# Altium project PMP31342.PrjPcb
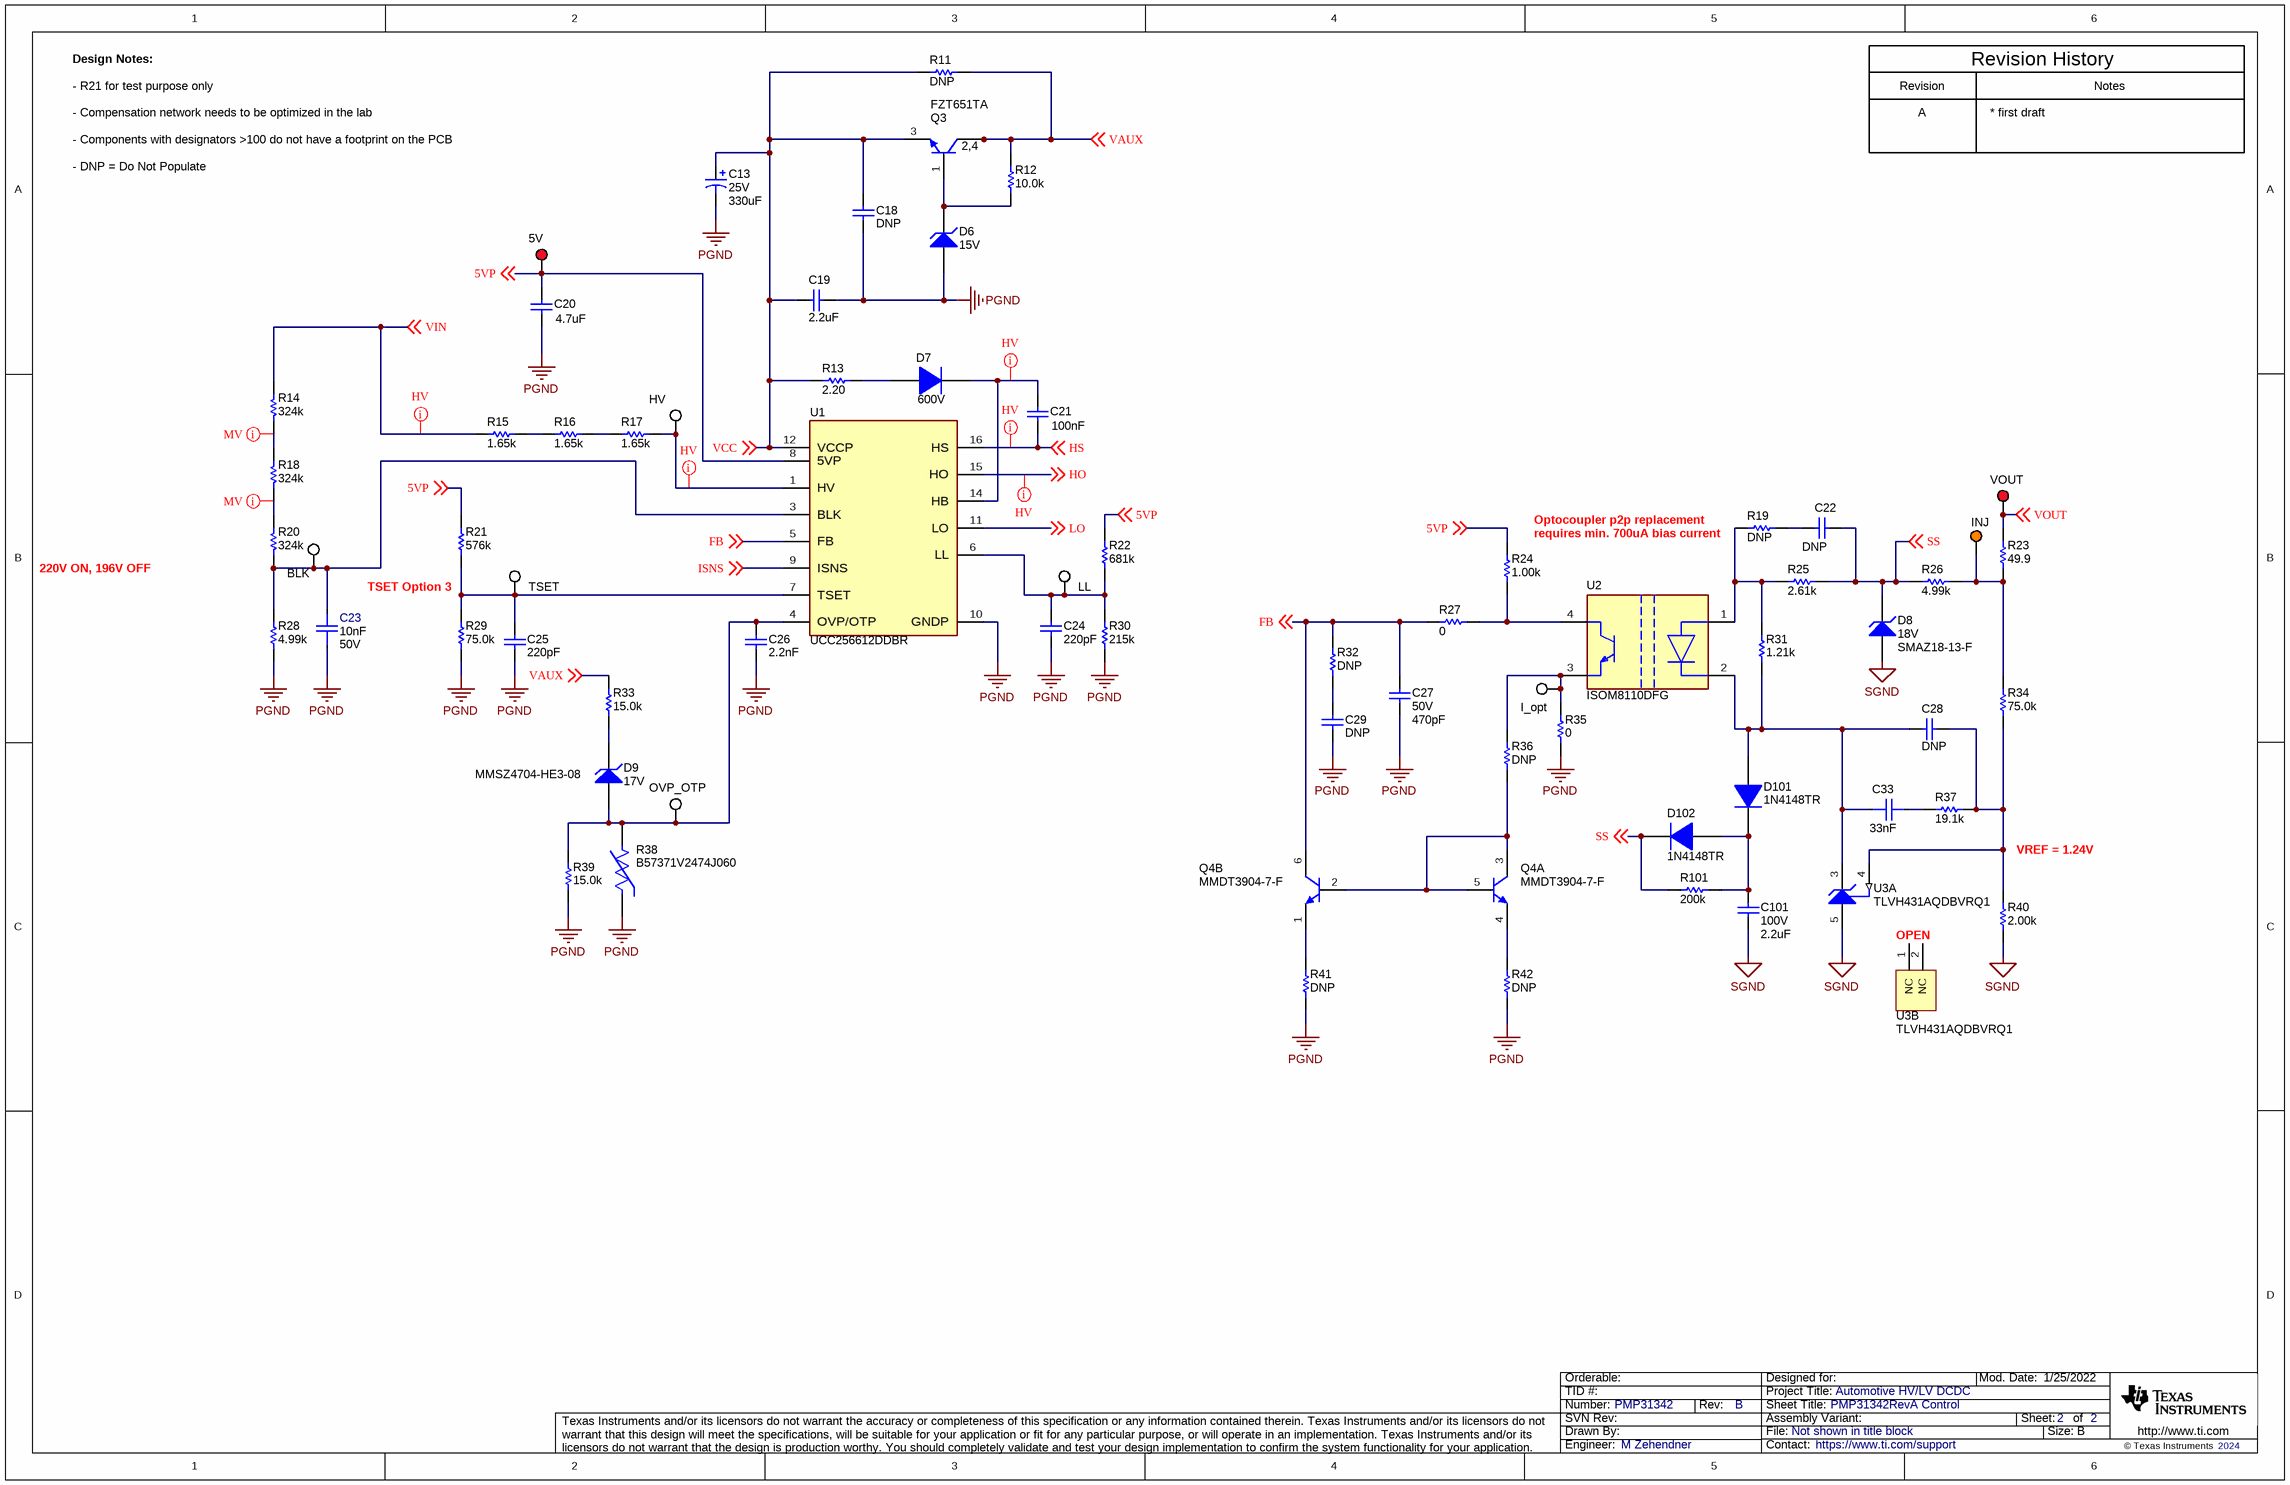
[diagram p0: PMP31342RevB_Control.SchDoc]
CopyrightYear: 2024; PRJ_Engineer: M Zehendner; PRJ_Number: PMP31342; PRJ_Title: Automotive HV/LV DCDC; SCH_Rev: B; TechSupport: https://www.ti.com/support
2 sheets, 137 parts. Net scope: global (net labels, ports and power ports of the same name join across sheets).
Board file: PMP31342RevA_PCB.PcbDoc
Sheets:
  PMP31342RevB_Control.SchDoc
  PMP31342RevB_PowerStage.SchDoc

## Sheet PMP31342RevB_Control.SchDoc: PMP31342RevA Control
size 431 x 279 mm; Date: Not shown in title block; ApprovedBy: Not shown in title block; CheckedBy: Not shown in title block; Author: Not shown in title block; CompanyName: Not shown in title block; Engineer: Not shown in title block; Organization: Not shown in title block; Address1: Not shown in title block; Address2: Not shown in title block; Address3: Not shown in title block; Address4: Not shown in title block; DocumentNumber: 2; Revision: Use project parameter SCH_Rev; SheetNumber: 2; SheetTotal: 2; PageSetup: Record=PageOptions¦CenterHorizontal=True¦CenterVertical=True¦PrintScale=1.00¦XCorrection=1.00¦YCorrection=1.00¦PrintKind=0¦BorderSize=5000000¦LeftOffset=0¦BottomOffset=0¦Orientation=2¦PaperLength=1000¦PaperWidth=1000¦Scale=100¦PaperSource=15¦PrintQuality=600¦MediaType=1¦DitherType=10¦PaperKind=Letter¦PrintScaleMode=1

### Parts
5V  5010  [Keystone5010]  (value not drawn)
BLK  5012  [Keystone5012]  (value not drawn)
C13  VDC_V: 25V  ValueDisplayed: 330uF  [SM_RADIAL_F]  (hidden comment: EEE-FK1E331P)
C18  ValueDisplayed: DNP  [0805L]  (hidden comment: C2012X7R1V225K085AC)
C19  ValueDisplayed: 2.2uF  [0805L]  (hidden comment: C2012X7R1V225K085AC)
C20  ValueDisplayed: 4.7uF  [1206L]  (hidden comment: C3216X7R1E475K085AB)
C21  Cap_F: 100nF  [1206_180L]  (hidden comment: GRM31C5C1E104JA01L)
C22  ValueDisplayed: DNP  [0603L]  (hidden comment: C0603C472J1GAC7867)
C23  Cap_F: 10nF  VDC_V: 50V  [FP-CGA3E2X7R1H103K080AA_0603-MFG]  (hidden comment: CGA3E2X7R1H103K080AA)
C24  Cap_F: 220pF  [0603]  (hidden comment: GRM188R72E221KW07D)
C25  Cap_F: 220pF  [0603]  (hidden comment: C0603X221K5RACTU)
C26  Cap_F: 2.2nF  [0603]  (hidden comment: C0603X222K5RACTU)
C27  VDC_V: 50V  ValueDisplayed: 470pF  [1206]  (hidden comment: CC1206KRX7R9BB471)
C28  Cap_F: DNP  [0603]  (hidden comment: GRM188R72A681KA01D)
C29  Cap_F: DNP  [0603]  (hidden comment: C0603X102K5RACTU)
C33  Cap_F: 33nF  [FP-CGA3E2X7R1H333K080AA_0603-MFG]  (hidden comment: CGA3E2X7R1H333K080AA)
C101  VDC_V: 100V  ValueDisplayed: 2.2uF  [1210_250]  (hidden comment: CGA6N3X7R2A225K230AB)
D6  value 15V  [SOD-123]  (hidden comment: MMSZ4702-HE3-08)
D7  Vr_V: 600V  [SMAF]  (hidden comment: ES1JAF)
D8  SMAZ18-13-F  value 18V  [SMA]
D9  MMSZ4704-HE3-08  value 17V  [SOD-123]
D101  1N4148TR  [DO-35]
D102  1N4148TR  [DO-35]
HV  5012  [Keystone5012]  (value not drawn)
I_opt  5012  [Keystone5012]  (value not drawn)
INJ  5013  [Keystone5013]  (value not drawn)
LL  5012  [Keystone5012]  (value not drawn)
OVP_OTP  5012  [Keystone5012]  (value not drawn)
Q3  FZT651TA  [SOT-223]
Q4  MMDT3904-7-F  [SOT-363]  (parts A,B of 2)
R11  ValueDisplayed: DNP  [0805_HV]  (hidden comment: CRCW08050000Z0EAHP)
R12  ValueDisplayed: 10.0k  [0603]  (hidden comment: CRCW060310K0FKEA)
R13  ValueDisplayed: 2.20  [0603L]  (hidden comment: ERJ-3RQF2R2V)
R14  ValueDisplayed: 324k  [1206]  (hidden comment: CRCW1206324KFKEA)
R15  ValueDisplayed: 1.65k  [1206L]  (hidden comment: CRCW12061K65FKEA)
R16  ValueDisplayed: 1.65k  [1206L]  (hidden comment: CRCW12061K65FKEA)
R17  ValueDisplayed: 1.65k  [1206L]  (hidden comment: CRCW12061K65FKEA)
R18  ValueDisplayed: 324k  [1206]  (hidden comment: CRCW1206324KFKEA)
R19  ValueDisplayed: DNP  [0603L]  (hidden comment: RC0603FR-071K21L)
R20  ValueDisplayed: 324k  [1206]  (hidden comment: CRCW1206324KFKEA)
R21  ValueDisplayed: 576k  [0603]  (hidden comment: CRCW0603576KFKEA)
R22  ValueDisplayed: 681k  [0603]  (hidden comment: CRCW0603681KFKEA)
R23  ValueDisplayed: 49.9  [0603]  (hidden comment: CRCW060349R9FKEA)
R24  ValueDisplayed: 1.00k  [0603]  (hidden comment: CRCW06031K00FKEA)
R25  ValueDisplayed: 2.61k  [0603]  (hidden comment: CRCW06032K61FKEA)
R26  ValueDisplayed: 4.99k  [0603]  (hidden comment: CRCW06034K99FKEA)
R27  ValueDisplayed: 0  [0402]  (hidden comment: CRCW04020000Z0ED)
R28  ValueDisplayed: 4.99k  [0603]  (hidden comment: CRCW06034K99FKEA)
R29  ValueDisplayed: 75.0k  [0603]  (hidden comment: CRCW060375K0FKEA)
R30  ValueDisplayed: 215k  [0603]  (hidden comment: CRCW0603215KFKEA)
R31  ValueDisplayed: 1.21k  [0603]  (hidden comment: CRCW06031K21FKEA)
R32  ValueDisplayed: DNP  [0603]  (hidden comment: CRCW06034K99FKEA)
R33  ValueDisplayed: 15.0k  [0603]  (hidden comment: RG1608P-153-B-T5)
R34  ValueDisplayed: 75.0k  [0603]  (hidden comment: CRCW060375K0FKEA)
R35  ValueDisplayed: 0  [0603]  (hidden comment: CRCW06030000Z0EA)
R36  ValueDisplayed: DNP  [0603]  (hidden comment: CRCW06030000Z0EA)
R37  ValueDisplayed: 19.1k  [0603]  (hidden comment: CRCW060319K1FKEA)
R38  B57371V2474J060  [FP-B57371V2474J060_0603-MFG]
R39  ValueDisplayed: 15.0k  [0603]  (hidden comment: RG1608P-153-B-T5)
R40  ValueDisplayed: 2.00k  [0603]  (hidden comment: CRCW06032K00FKEA)
R41  ValueDisplayed: DNP  [0603]  (hidden comment: CRCW06030000Z0EA)
R42  ValueDisplayed: DNP  [0603]  (hidden comment: CRCW06030000Z0EA)
R101  ValueDisplayed: 200k  [0402]  (hidden comment: CRCW0402200KJNED)
TSET  5012  [Keystone5012]  (value not drawn)
U1  PartNumber: UCC256612DDBR  [DDB0014A-MFG]  (hidden comment: UCC256602DDBR)
U2  ISOM8110DFG  [DFG0004A-MFG]
U3  TLVH431AQDBVRQ1  [DBV0005A_N]  (parts A,B of 2)
VOUT  5010  [Keystone5010]  (value not drawn)

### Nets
PGND: C13.2(-) C18.1 C19.2 C20.2 C23.1 C24.2 C25.2 C26.2 C27.2 C29.2 D6.2(A) R28.1 R29.1 R30.1 R35.1 R38.1 R39.1 R41.1 R42.1 U1.10(GNDP)
SGND: C101.2 D8.2(A) R40.1 U3.5(ANODE)
5VP: 5V.1 C20.1 R21.2 R22.2 R24.2 U1.8(5VP) ; off-sheet 5VP
FB: C27.1 Q4.6(C) R27.1 R32.2 U1.5(FB) ; off-sheet FB
HO: U1.15(HO) ; off-sheet HO
HS: C21.2 U1.16(HS) ; off-sheet HS
ISNS: U1.9(ISNS) ; off-sheet ISNS
LO: U1.11(LO) ; off-sheet LO
SS: C22.1 D8.1(K) D102.1(K) R25.2 R26.1 R101.1 ; off-sheet SS
VAUX: Q3.2(C) Q3.4(C) R11.2 R12.2 R33.2 ; off-sheet VAUX
VCC: C13.1(+) C18.2 C19.1 Q3.3(E) R11.1 R13.1 U1.12(VCCP) ; off-sheet VCC
VIN: R14.2 R15.1 ; off-sheet VIN
VOUT: R23.2 VOUT.1 ; off-sheet VOUT
NetBLK_1: BLK.1 C23.2 R20.1 R28.2 U1.3(BLK)
NetC21_1: C21.1 D7.1(K) U1.14(HB)
NetC22_2: C22.2 R19.2
NetC24_1: C24.1 LL.1 R22.1 R30.2 U1.6(LL)
NetC25_1: C25.1 R21.1 R29.2 TSET.1 U1.7(TSET)
NetC26_1: C26.1 D9.2(A) OVP_OTP.1 R38.2 R39.2 U1.4(OVP/OTP)
NetC28_1: C28.1 R34.1 R37.2 R40.2 U3.4(REF)
NetC28_2: C28.2 C33.1 D101.2(A) R31.1 U2.2(CAT) U3.3(CATHODE)
NetC29_1: C29.1 R32.1
NetC33_2: C33.2 R37.1
NetC101_1: C101.1 D101.1(K) D102.2(A) R101.2
NetD6_1: D6.1(K) Q3.1(B) R12.1
NetD7_2: D7.2(A) R13.2
NetD9_1: D9.1(K) R33.1
NetHV_1: HV.1 R17.2 U1.1(HV)
NetI_opt_1: I_opt.1 R35.2 R36.2 U2.3(Emitter)
NetINJ_1: INJ.1 R23.1 R26.2 R34.2
NetQ4_1: Q4.1(E) R41.2
NetQ4_2: Q4.2(B) Q4.3(C) Q4.5(B) R36.1
NetQ4_4: Q4.4(E) R42.2
NetR14_1: R14.1 R18.2
NetR15_2: R15.2 R16.1
NetR16_2: R16.2 R17.1
NetR18_1: R18.1 R20.2
NetR19_1: R19.1 R25.1 R31.2 U2.1(AN)
NetR24_1: R24.1 R27.2 U2.4(Collector)

Not connected (* = marked no-connect by the designer): U3 1(NC) 2(NC)

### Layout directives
net class HV: HO, HS, NetC21_1, NetHV_1, VIN
net class MV: NetR14_1, NetR18_1

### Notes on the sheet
- Design Notes:
- - R21 for test purpose only
- Revision
- Revision History
- Notes
- - DNP = Do Not Populate
- - Compensation network needs to be optimized in the lab
- - Components with designators >100 do not have a footprint on the PCB
- A
- * first draft
- (near R20) 220V ON, 196V OFF
- Optocoupler p2p replacement
- requires min. 700uA bias current
- TSET Option 3
- VREF = 1.24V
- (near U3) OPEN

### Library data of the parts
5V VOUT = CMP-0055147-2: Test Point, Multipurpose, Red, TH; Manufacturer: Keystone Electronics; CNHeader: FALSE; Green_Lifecycle: Active; Green_REACh: Passed; ContactFinish: Silver; CT: TRUE
BLK HV I_opt LL OVP_OTP TSET = CMP-0055149-2: Test Point, Multipurpose, White, TH; Manufacturer: Keystone Electronics; CNHeader: FALSE; Green_Lifecycle: Active; Green_REACh: Passed; ContactFinish: Silver; CT: TRUE
C13 = CMP-0010717-1: CAP, AL, 330 uF, 25 V, +/- 20%, 0.16 ohm, AEC-Q200 Grade 2, SMD; Manufacturer: Panasonic; TaMin_C: -55°C; ESR_ohm: 0.16; Polarized: Y; SizeAreaWB_mm2: 123.6; U/M: EA; Value: 330uF; TaMax_C: 105°C; SizeZ_mm: 10.2; SizeX_mm: 10; SizeY_mm: 8.3; Cap_Case: F; SizeArea_mm2: 83; CompType: Capacitor; Cap_F: 330µF; IRMS_A: 600mA; AEC Grade: 2; AEC Category: Q200
C18 C19 = CMP-0007883-2: CAP, CERM, 2.2 uF, 35 V, +/- 10%, X7R, 0805; Manufacturer: TDK; TaMin_C: -55°C; Polarized: N; SizeAreaWB_mm2: 6.75; Value1: Unknown; U/M: EA; Value: 2.2uF; TaMax_C: 125°C; SizeZ_mm: 1.45; SizeX_mm: 2; SizeY_mm: 1.25; Cap_Case: 0805; Value2: 35V; SizeArea_mm2: 2.5; CompType: Capacitor; Cap_F: 2.2µF; AEC Category: Q200
C20 = CMP-0008693-2: CAP, CERM, 4.7 uF, 25 V, +/- 10%, X7R, 1206; Manufacturer: TDK; TaMin_C: -55°C; Polarized: N; SizeAreaWB_mm2: 10.92; Value1: Unknown; U/M: EA; Value: 4.7uF; TaMax_C: 125°C; SizeZ_mm: 1.35; SizeX_mm: 3.2; SizeY_mm: 1.6; Cap_Case: 1206; Value2: 25V; SizeArea_mm2: 5.12; CompType: Capacitor; Cap_F: 4.7µF; AEC Category: Q200
C21 = CMP-0064950-2: CAP, CERM, 0.1 uF, 25 V,+/- 5%, C0G/NP0, 1206; Manufacturer: MuRata; TaMin_C: -55°C; Polarized: N; SizeAreaWB_mm2: 10.92; Value1: Unknown; U/M: EA; Value: 0.1uF; TaMax_C: 125°C; SizeZ_mm: 1.8; SizeX_mm: 3.2; SizeY_mm: 1.6; Cap_Case: 1206; Value2: 25V; SizeArea_mm2: 5.12; AEC Category: Q200
C22 = CMP-0006941-4: CAP, CERM, 4700 pF, 100 V, +/- 5%, C0G/NP0, 0603; Manufacturer: Kemet; TaMin_C: -55°C; Polarized: N; SizeAreaWB_mm2: 4.68; Value1: Unknown; U/M: EA; Value: 4700pF; TaMax_C: 125°C; SizeZ_mm: 1; SizeX_mm: 1.6; SizeY_mm: 0.8; Cap_Case: 0603; Value2: 100V; SizeArea_mm2: 1.28; Cap_F: 4.7nF; AEC Category: Q200
C23 = CMP-0097473-1: Cap Ceramic 10nF 50V X7R 10% Pad SMD 0603 +125°C Automotive T/R; Manufacturer: TDK; TempCo: 0.15; AEC Grade: Grade 1; Tolerance_%: 0.1%; AEC Qualified: Yes; SizeZ_mm: 1.1mm
C24 = CMP-0007492-4: CAP, CERM, 220 pF, 250 V, +/- 10%, X7R, 0603; Manufacturer: MuRata; TaMin_C: -55°C; Polarized: N; SizeAreaWB_mm2: 4.68; Value1: Unknown; U/M: EA; Value: 220pF; TaMax_C: 125°C; SizeZ_mm: 1; SizeX_mm: 1.6; SizeY_mm: 0.8; Value2: 250V; SizeArea_mm2: 1.28; AEC Category: Q200
C25 = CMP-0006982-4: CAP, CERM, 220 pF, 50 V, +/- 10%, X7R, 0603; Manufacturer: Kemet; TaMin_C: -55°C; Polarized: N; SizeAreaWB_mm2: 4.68; Value1: Unknown; U/M: EA; Value: 220pF; TaMax_C: 125°C; SizeZ_mm: 1; SizeX_mm: 1.6; SizeY_mm: 0.8; Value2: 50V; SizeArea_mm2: 1.28; AEC Category: Q200
C26 = CMP-0006983-4: CAP, CERM, 2200 pF, 50 V, +/- 10%, X7R, 0603; Manufacturer: Kemet; TaMin_C: -55°C; Polarized: N; SizeAreaWB_mm2: 4.68; Value1: Unknown; U/M: EA; Value: 2200pF; TaMax_C: 125°C; SizeZ_mm: 1; SizeX_mm: 1.6; SizeY_mm: 0.8; Value2: 50V; SizeArea_mm2: 1.28; AEC Category: Q200
C27 = CMP-0008758-2: CAP, CERM, 470 pF, 50 V, +/- 10%, X7R, 1206; Manufacturer: Yageo America; TaMin_C: -55°C; Polarized: N; SizeAreaWB_mm2: 10.92; Value1: Unknown; U/M: EA; Value: 470pF; TaMax_C: 125°C; SizeZ_mm: 1.35; SizeX_mm: 3.2; SizeY_mm: 1.6; SizeArea_mm2: 5.12; AEC Category: Q200
C28 = CMP-0007486-5: CAP, CERM, 680 pF, 100 V, +/- 10%, X7R, 0603; Manufacturer: MuRata; TaMin_C: -55°C; Polarized: N; SizeAreaWB_mm2: 4.68; Value1: Unknown; U/M: EA; Value: 680pF; TaMax_C: 125°C; SizeZ_mm: 1; SizeX_mm: 1.6; SizeY_mm: 0.8; Value2: 100V; SizeArea_mm2: 1.28; AEC Category: Q200
C29 = CMP-0006976-5: CAP, CERM, 1000 pF, 50 V, +/- 10%, X7R, 0603; Manufacturer: Kemet; TaMin_C: -55°C; Polarized: N; SizeAreaWB_mm2: 4.68; Value1: Unknown; U/M: EA; Value: 1000pF; TaMax_C: 125°C; SizeZ_mm: 1; SizeX_mm: 1.6; SizeY_mm: 0.8; Value2: 50V; SizeArea_mm2: 1.28; AEC Category: Q200
C33 = CMP-0090210-1: Cap Ceramic 33nF 50V X7R 10% Pad SMD 0603 +125°C Automotive T/R; Manufacturer: TDK; AEC Qualified: Yes; AEC Grade: Grade 1; Tolerance_%: 0.1%; TempCo: 0.15; SizeZ_mm: 1.1mm
C101 = CMP-0009152-2: CAP, CERM, 2.2 uF, 100 V, +/- 10%, X7R, AEC-Q200 Grade 1,; Manufacturer: TDK; TaMin_C: -55°C; ESR_ohm: 1.73m; Polarized: N; SizeAreaWB_mm2: 14.7; Value1: 0.00173 ohm; U/M: EA; Value: 2.2uF; TaMax_C: 125°C; SizeZ_mm: 2.5; SizeX_mm: 3.2; SizeArea_mm2: 8; AEC Qualified: Y; Cap_F: 2.2µF; IRMS_A: 5.5932A; AEC Grade: 1; AEC Category: Q200
D6 = CMP-0077575-3: Diode, Zener, 15 V, 500 mW, AEC-Q101, SOD-123; Manufacturer: Vishay-Semiconductor; SizeAreaWB_mm2: 13.095; Power_W: 500mW; AEC Category: Q101; SizeX_mm: 3.85; Value1: 0.5W; SizeZ_mm: 1.35; AEC Qualified: Y; SizeY_mm: 1.7; SizeArea_mm2: 6.545; RJA_CperW: 340
D7 = CMP-0029162-2: Diode, Ultrafast, 600 V, 1 A, AEC-Q101, SMAF; Manufacturer: Fairchild Semiconductor; Io_A: 1A; Green_Lifecycle: Not Set; SizeAreaWB_mm2: 19.95; Green_REACh: Incomplete; TJmax_C: 150°C; Value: 600V; SizeZ_mm: 1; SizeX_mm: 4.7; SizeY_mm: 2.5; Vf_V: 1.7V; SizeArea_mm2: 11.75; AEC Qualified: Y; AEC Category: Q101
D8 = CMP-0005526-4: Diode, Zener, 18 V, 1 W, AEC-Q101, SMA; Manufacturer: Diodes Inc.; SizeAreaWB_mm2: 37.3428; AEC Category: Q101; Power_W: 1W; SizeY_mm: 2.92; SizeZ_mm: 2.87; SizeX_mm: 5.59; SizeArea_mm2: 16.3228; AEC Qualified: Y; RJA_CperW: 125
D9 = CMP-0077577-3: Diode, Zener, 17 V, 500 mW, AEC-Q101, SOD-123; Manufacturer: Vishay-Semiconductor; SizeX_mm: 3.85; Power_W: 500mW; SizeY_mm: 1.7; AEC Category: Q101; SizeAreaWB_mm2: 13.095; Value1: 0.5W; SizeArea_mm2: 6.545; AEC Qualified: Y; SizeZ_mm: 1.35; RJA_CperW: 340
D101 D102 = CMP-0029198-2: Diode, P-N, 100 V, 0.2 A, TH; Manufacturer: Fairchild Semiconductor; SizeArea_mm2: 13.95; Vr_V: 100V; SizeX_mm: 9.3; Value: 100V; SizeY_mm: 1.5; Io_A: 200mA; TJmax_C: 175°C; AEC Qualified: N; AEC Category: Q101; Value1: 0.2A; SizeZ_mm: 1.7; SizeAreaWB_mm2: 39.55
INJ = CMP-0055150-2: Test Point, Multipurpose, Orange, TH; Manufacturer: Keystone Electronics; CNHeader: FALSE; Green_Lifecycle: Active; Green_REACh: Passed; ContactFinish: Silver; CT: TRUE
Q3 = CMP-0000393-2: Transistor, NPN, 60 V, 3 A, SOT-223; Manufacturer: Zetex; TaMax_C: 150°C; Value2: 300; Value1: 3 A; Vcesat1_V: 430mV; SizeX_mm: 6.5; SizeY_mm: 7; TaMin_C: -55°C; IcRated_A: 3A; CompType: BJT; SizeZ_mm: 1.6; Value: 60 V; SizeArea_mm2: 45.5; NPN: 1; Vceo_V: 60V; PNP: 0; AEC Category: Q101; SizeAreaWB_mm2: 76.5; U/M: EA
Q4 = CMP-0000396-2: Transistor, Dual NPN, 40 V, 0.2 A, SOT-363; Manufacturer: Diodes Inc.; TaMax_C: 150°C; Value2: 300; Value1: 0.2 A; Vcesat1_V: 300mV; SizeX_mm: 2.2; TaMin_C: -55°C; IcRated_A: 200mA; CompType: BJT; SizeZ_mm: 1.1; Value: 40 V; SizeArea_mm2: 4.84; NPN: 2; Vceo_V: 40V; PNP: 0; AEC Category: Q101; SizeAreaWB_mm2: 10.24; U/M: EA
R11 = CMP-0020443-3: RES, 0, 5%, 0.333 W, AEC-Q200 Grade 0, 0805; Manufacturer: Vishay-Dale; Power_W: 333mW; TempCo: 200 ppm/C; Value_Code: 0000; Value: 0; EIA_Code: E24; SizeX_mm: 2; SizeY_mm: 1.25; SizeZ_mm: 1.45; Value2: 0.333W; SizeArea_mm2: 2.5; AEC Qualified: Y; AEC Category: Q200; VDC_V: 150V
R12 = CMP-0021998-4: RES, 10.0 k, 1%, 0.1 W, AEC-Q200 Grade 0, 0603; Manufacturer: Vishay-Dale; Power_W: 100mW; TempCo: 100 ppm/C; Value_Code: 10k0; Value: 10.0k; EIA_Code: E96; Res_ohm: 10k; SizeX_mm: 1.6; SizeY_mm: 0.8; SizeZ_mm: 1; Value2: 0.1W; SizeArea_mm2: 1.28; AEC Qualified: Y; VDC_V: 75V; AEC Category: Q200; AEC Grade: 0
R13 = CMP-0022711-2: RES, 2.20, 1%, 0.1 W, 0603; Manufacturer: Panasonic; Power_W: 100mW; TempCo: 200 ppm/C; Value_Code: 2R20; U/M: EA; Value: 2.20; Res_ohm: 2.2; SizeX_mm: 1.6; SizeY_mm: 0.8; SizeZ_mm: 1; Value2: 0.1W; SizeArea_mm2: 1.28; CompType: Resistor; AEC Category: Q200
R14 R18 R20 = CMP-0016907-3: RES, 324 k, 1%, 0.25 W, AEC-Q200 Grade 0, 1206; Manufacturer: Vishay-Dale; Power_W: 250mW; TempCo: 100 ppm/C; Value: 324k; EIA_Code: E96; SizeX_mm: 3.2; SizeY_mm: 1.6; SizeZ_mm: 1.35; Value2: 0.25W; SizeArea_mm2: 5.12; AEC Qualified: Y; VDC_V: 200V; AEC Category: Q200; AEC Grade: 0
R15-R17 = CMP-0016708-3: RES, 1.65 k, 1%, 0.25 W, AEC-Q200 Grade 0, 1206; Manufacturer: Vishay-Dale; Power_W: 250mW; TempCo: 100 ppm/C; Value_Code: 1k65; Value: 1.65k; EIA_Code: E96; SizeX_mm: 3.2; SizeY_mm: 1.6; SizeZ_mm: 1.35; Value2: 0.25W; SizeArea_mm2: 5.12; CompType: Resistor; AEC Qualified: Y; VDC_V: 200V; AEC Category: Q200; AEC Grade: 0
R19 = CMP-0022871-5: RES, 1.21 k, 1%, 0.1 W, 0603; Manufacturer: Yageo; Power_W: 100mW; TempCo: 100 ppm/C; Value_Code: 1k21; Value: 1.21k; EIA_Code: E96; SizeX_mm: 1.6; SizeY_mm: 0.8; SizeZ_mm: 1; Value2: 0.1W; SizeArea_mm2: 1.28; AEC Qualified: N; VDC_V: 75V; AEC Category: Q200; SizeAreaWB_mm2: 4.68
R21 = CMP-0022501-4: RES, 576 k, 1%, 0.1 W, AEC-Q200 Grade 0, 0603; Manufacturer: Vishay-Dale; Power_W: 100mW; TempCo: 100 ppm/C; Value: 576k; EIA_Code: E96; SizeX_mm: 1.6; SizeY_mm: 0.8; SizeZ_mm: 1; Value2: 0.1W; SizeArea_mm2: 1.28; AEC Qualified: Y; VDC_V: 75V; AEC Category: Q200; AEC Grade: 0
R22 = CMP-0022550-4: RES, 681 k, 1%, 0.1 W, AEC-Q200 Grade 0, 0603; Manufacturer: Vishay-Dale; Power_W: 100mW; TempCo: 100 ppm/C; Value: 681k; EIA_Code: E96; SizeX_mm: 1.6; SizeY_mm: 0.8; SizeZ_mm: 1; Value2: 0.1W; SizeArea_mm2: 1.28; AEC Qualified: Y; VDC_V: 75V; AEC Category: Q200; AEC Grade: 0
R23 = CMP-0022448-4: RES, 49.9, 1%, 0.1 W, AEC-Q200 Grade 0, 0603; Manufacturer: Vishay-Dale; Power_W: 100mW; TempCo: 100 ppm/C; Value_Code: 49R9; Value: 49.9; EIA_Code: E96; SizeX_mm: 1.6; SizeY_mm: 0.8; SizeZ_mm: 1; Value2: 0.1W; SizeArea_mm2: 1.28; AEC Qualified: Y; VDC_V: 75V; AEC Category: Q200; AEC Grade: 0
R24 = CMP-0022109-5: RES, 1.00 k, 1%, 0.1 W, AEC-Q200 Grade 0, 0603; Manufacturer: Vishay-Dale; Power_W: 100mW; TempCo: 100 ppm/C; Value_Code: 1k00; Value: 1.00k; EIA_Code: E96; Res_ohm: 1k; SizeX_mm: 1.6; SizeY_mm: 0.8; SizeZ_mm: 1; Value2: 0.1W; SizeArea_mm2: 1.28; AEC Qualified: Y; VDC_V: 75V; AEC Category: Q200; AEC Grade: 0
R25 = CMP-0022279-4: RES, 2.61 k, 1%, 0.1 W, AEC-Q200 Grade 0, 0603; Manufacturer: Vishay-Dale; Power_W: 100mW; TempCo: 100 ppm/C; Value_Code: 2k61; Value: 2.61k; EIA_Code: E96; SizeX_mm: 1.6; SizeY_mm: 0.8; SizeZ_mm: 1; Value2: 0.1W; SizeArea_mm2: 1.28; AEC Qualified: Y; VDC_V: 75V; AEC Category: Q200; AEC Grade: 0
R26 R28 R32 = CMP-0022458-4: RES, 4.99 k, 1%, 0.1 W, AEC-Q200 Grade 0, 0603; Manufacturer: Vishay-Dale; Power_W: 100mW; TempCo: 100 ppm/C; Value_Code: 4k99; Value: 4.99k; EIA_Code: E96; SizeX_mm: 1.6; SizeY_mm: 0.8; SizeZ_mm: 1; Value2: 0.1W; SizeArea_mm2: 1.28; AEC Qualified: Y; VDC_V: 75V; AEC Category: Q200; AEC Grade: 0
R27 = CMP-0026822-3: RES, 0, 5%, 0.063 W, AEC-Q200 Grade 0, 0402; Manufacturer: Vishay-Dale; Power_W: 63mW; TempCo: 200 ppm/C; Value_Code: 0000; Value: 0; EIA_Code: E24; SizeX_mm: 1; SizeY_mm: 0.5; SizeZ_mm: 0.6; Value2: 0.063W; AEC Qualified: Y; VDC_V: 50V; AEC Category: Q200
R29 R34 = CMP-0022589-4: RES, 75.0 k, 1%, 0.1 W, AEC-Q200 Grade 0, 0603; Manufacturer: Vishay-Dale; Power_W: 100mW; TempCo: 100 ppm/C; Value_Code: 75k0; Value: 75.0k; EIA_Code: E96; Res_ohm: 75k; SizeX_mm: 1.6; SizeY_mm: 0.8; SizeZ_mm: 1; Value2: 0.1W; SizeArea_mm2: 1.28; AEC Qualified: Y; VDC_V: 75V; AEC Category: Q200; AEC Grade: 0
R30 = CMP-0022210-4: RES, 215 k, 1%, 0.1 W, AEC-Q200 Grade 0, 0603; Manufacturer: Vishay-Dale; Power_W: 100mW; TempCo: 100 ppm/C; Value: 215k; EIA_Code: E96; SizeX_mm: 1.6; SizeY_mm: 0.8; SizeZ_mm: 1; Value2: 0.1W; SizeArea_mm2: 1.28; AEC Qualified: Y; VDC_V: 75V; AEC Category: Q200; AEC Grade: 0
R31 = CMP-0022117-4: RES, 1.21 k, 1%, 0.1 W, AEC-Q200 Grade 0, 0603; Manufacturer: Vishay-Dale; Power_W: 100mW; TempCo: 100 ppm/C; Value_Code: 1k21; Value: 1.21k; EIA_Code: E96; SizeX_mm: 1.6; SizeY_mm: 0.8; SizeZ_mm: 1; Value2: 0.1W; SizeArea_mm2: 1.28; AEC Qualified: Y; VDC_V: 75V; AEC Category: Q200; AEC Grade: 0
R33 R39 = CMP-0023441-3: RES, 15.0 k, 0.1%, 0.1 W, 0603; Manufacturer: Susumu Co Ltd; Power_W: 100mW; TempCo: 25 ppm/C; Value_Code: 15k0; U/M: EA; Value: 15.0k; EIA_Code: E192; Res_ohm: 15k; SizeX_mm: 1.6; SizeY_mm: 0.8; SizeZ_mm: 1; Value2: 0.1W; SizeArea_mm2: 1.28; VDC_V: 75V; AEC Category: Q200
R35 R36 R41 R42 = CMP-0025697-4: RES, 0, 5%, 0.1 W, AEC-Q200 Grade 0, 0603; Manufacturer: Vishay-Dale; Power_W: 100mW; TempCo: 200 ppm/C; Value_Code: 0000; Value: 0; EIA_Code: E24; SizeX_mm: 1.6; SizeY_mm: 0.8; SizeZ_mm: 1; Value2: 0.1W; SizeArea_mm2: 1.28; AEC Qualified: Y; VDC_V: 75V; AEC Category: Q200
R37 = CMP-0022105-4: RES, 19.1 k, 1%, 0.1 W, AEC-Q200 Grade 0, 0603; Manufacturer: Vishay-Dale; Power_W: 100mW; TempCo: 100 ppm/C; Value_Code: 19k1; Value: 19.1k; EIA_Code: E96; SizeX_mm: 1.6; SizeY_mm: 0.8; SizeZ_mm: 1; Value2: 0.1W; SizeArea_mm2: 1.28; AEC Qualified: Y; VDC_V: 75V; AEC Category: Q200; AEC Grade: 0
R38 = CMP-0096703-1: NTC Thermistor 470k 0603 (1608 Metric); Manufacturer: TDK; AEC Qualified: No; Res_ohm: 470kΩ; Power_W: 180mW; B 25 50: 4386K; B 25 100: 4480K; SizeZ_mm: 0.9mm; B 25 85: 4455K; B Tolerance: 3%; Tolerance_%: 5%
R40 = CMP-0022268-4: RES, 2.00 k, 1%, 0.1 W, AEC-Q200 Grade 0, 0603; Manufacturer: Vishay-Dale; Power_W: 100mW; TempCo: 100 ppm/C; Value_Code: 2k00; Value: 2.00k; EIA_Code: E96; Res_ohm: 2k; SizeX_mm: 1.6; SizeY_mm: 0.8; SizeZ_mm: 1; Value2: 0.1W; SizeArea_mm2: 1.28; AEC Qualified: Y; VDC_V: 75V; AEC Category: Q200; AEC Grade: 0
R101 = CMP-0026873-2: RES, 200 k, 5%, 0.063 W, AEC-Q200 Grade 0, 0402; Manufacturer: Vishay-Dale; Power_W: 63mW; TempCo: 200 ppm/C; Value: 200k; EIA_Code: E24; SizeX_mm: 1; SizeY_mm: 0.5; SizeZ_mm: 0.6; Value2: 0.063W; AEC Qualified: Y; VDC_V: 50V; AEC Category: Q200; AEC Grade: 0
U1 = CMP-0095298-2: 750kHz Wide VIN/VOUT Range LLC Controller Optimized for Light Load Efficiency; Manufacturer: Texas Instruments; Output Type: Other; Switching Frequency: 30-750kHz; TJmax_C: +150°C; SizeZ_mm: 1.75mm; AEC Qualified: No; Standoff Height: 0.1mm; Number Of Outputs: 2; TaMax_C: +125°C; TaMin_C: -40°C; Max Supply Voltage: 18.5V; AEC Category: Q200; CompType: IC
U2 = CMP-0098363-1: 3.75-kVRMS, Single-Channel Opto-Emulator with Transistor Output; Manufacturer: Texas Instruments; SizeZ_mm: 2.65mm; AEC Qualified: No; CTR (Max): 160%; CTR (Min): 80%; Emiiter Collector Voltage: 7V; Forward Current: 10mA; Power_TotalModule: 200mW; Standoff Height: 0.05mm; TaMax_C: +125°C; TaMin_C: -55°C; TJmax_C: +150°C; Turn Off Delay Time: 5us; Turn On Delay Time: 1.7us; Value: 80V; Vf_V: 1.1V; Voltage_Isolation_Vrms: 3750Vrms
U3 = CMP-0032955-1: Automotive Catalog Low-Voltage Adjustable Precision Shunt Regulator, 80 mA, -40 to 125 degC, 5-pin SOT-23 (DBV), Green (RoHS & no Sb/Br); Manufacturer: Texas Instruments; Iout/Iz(Max)(mA): 80; VO Adj(Max)(V): 18; SubFamily: Shunt Voltage Reference; Temp Coeff(Max)(ppm/ degree C): 129; VO Adj(Min)(V): 1.24; Initial Accuracy @ 25/deg C(%): 1

## Sheet PMP31342RevB_PowerStage.SchDoc: PMP31342RevA Power Stage
size 431 x 279 mm; Date: Not shown in title block; ApprovedBy: Not shown in title block; CheckedBy: Not shown in title block; Author: Not shown in title block; CompanyName: Not shown in title block; Engineer: Not shown in title block; Organization: Not shown in title block; Address1: Not shown in title block; Address2: Not shown in title block; Address3: Not shown in title block; Address4: Not shown in title block; DocumentNumber: 1; Revision: Use project parameter SCH_Rev; SheetNumber: 1; SheetTotal: 2; PageSetup: Record=PageOptions¦CenterHorizontal=True¦CenterVertical=True¦PrintScale=1.00¦XCorrection=1.00¦YCorrection=1.00¦PrintKind=0¦BorderSize=5000000¦LeftOffset=0¦BottomOffset=0¦Orientation=2¦PaperLength=1000¦PaperWidth=1000¦Scale=100¦PaperSource=15¦PrintQuality=600¦MediaType=1¦DitherType=10¦PaperKind=Letter¦PrintScaleMode=1
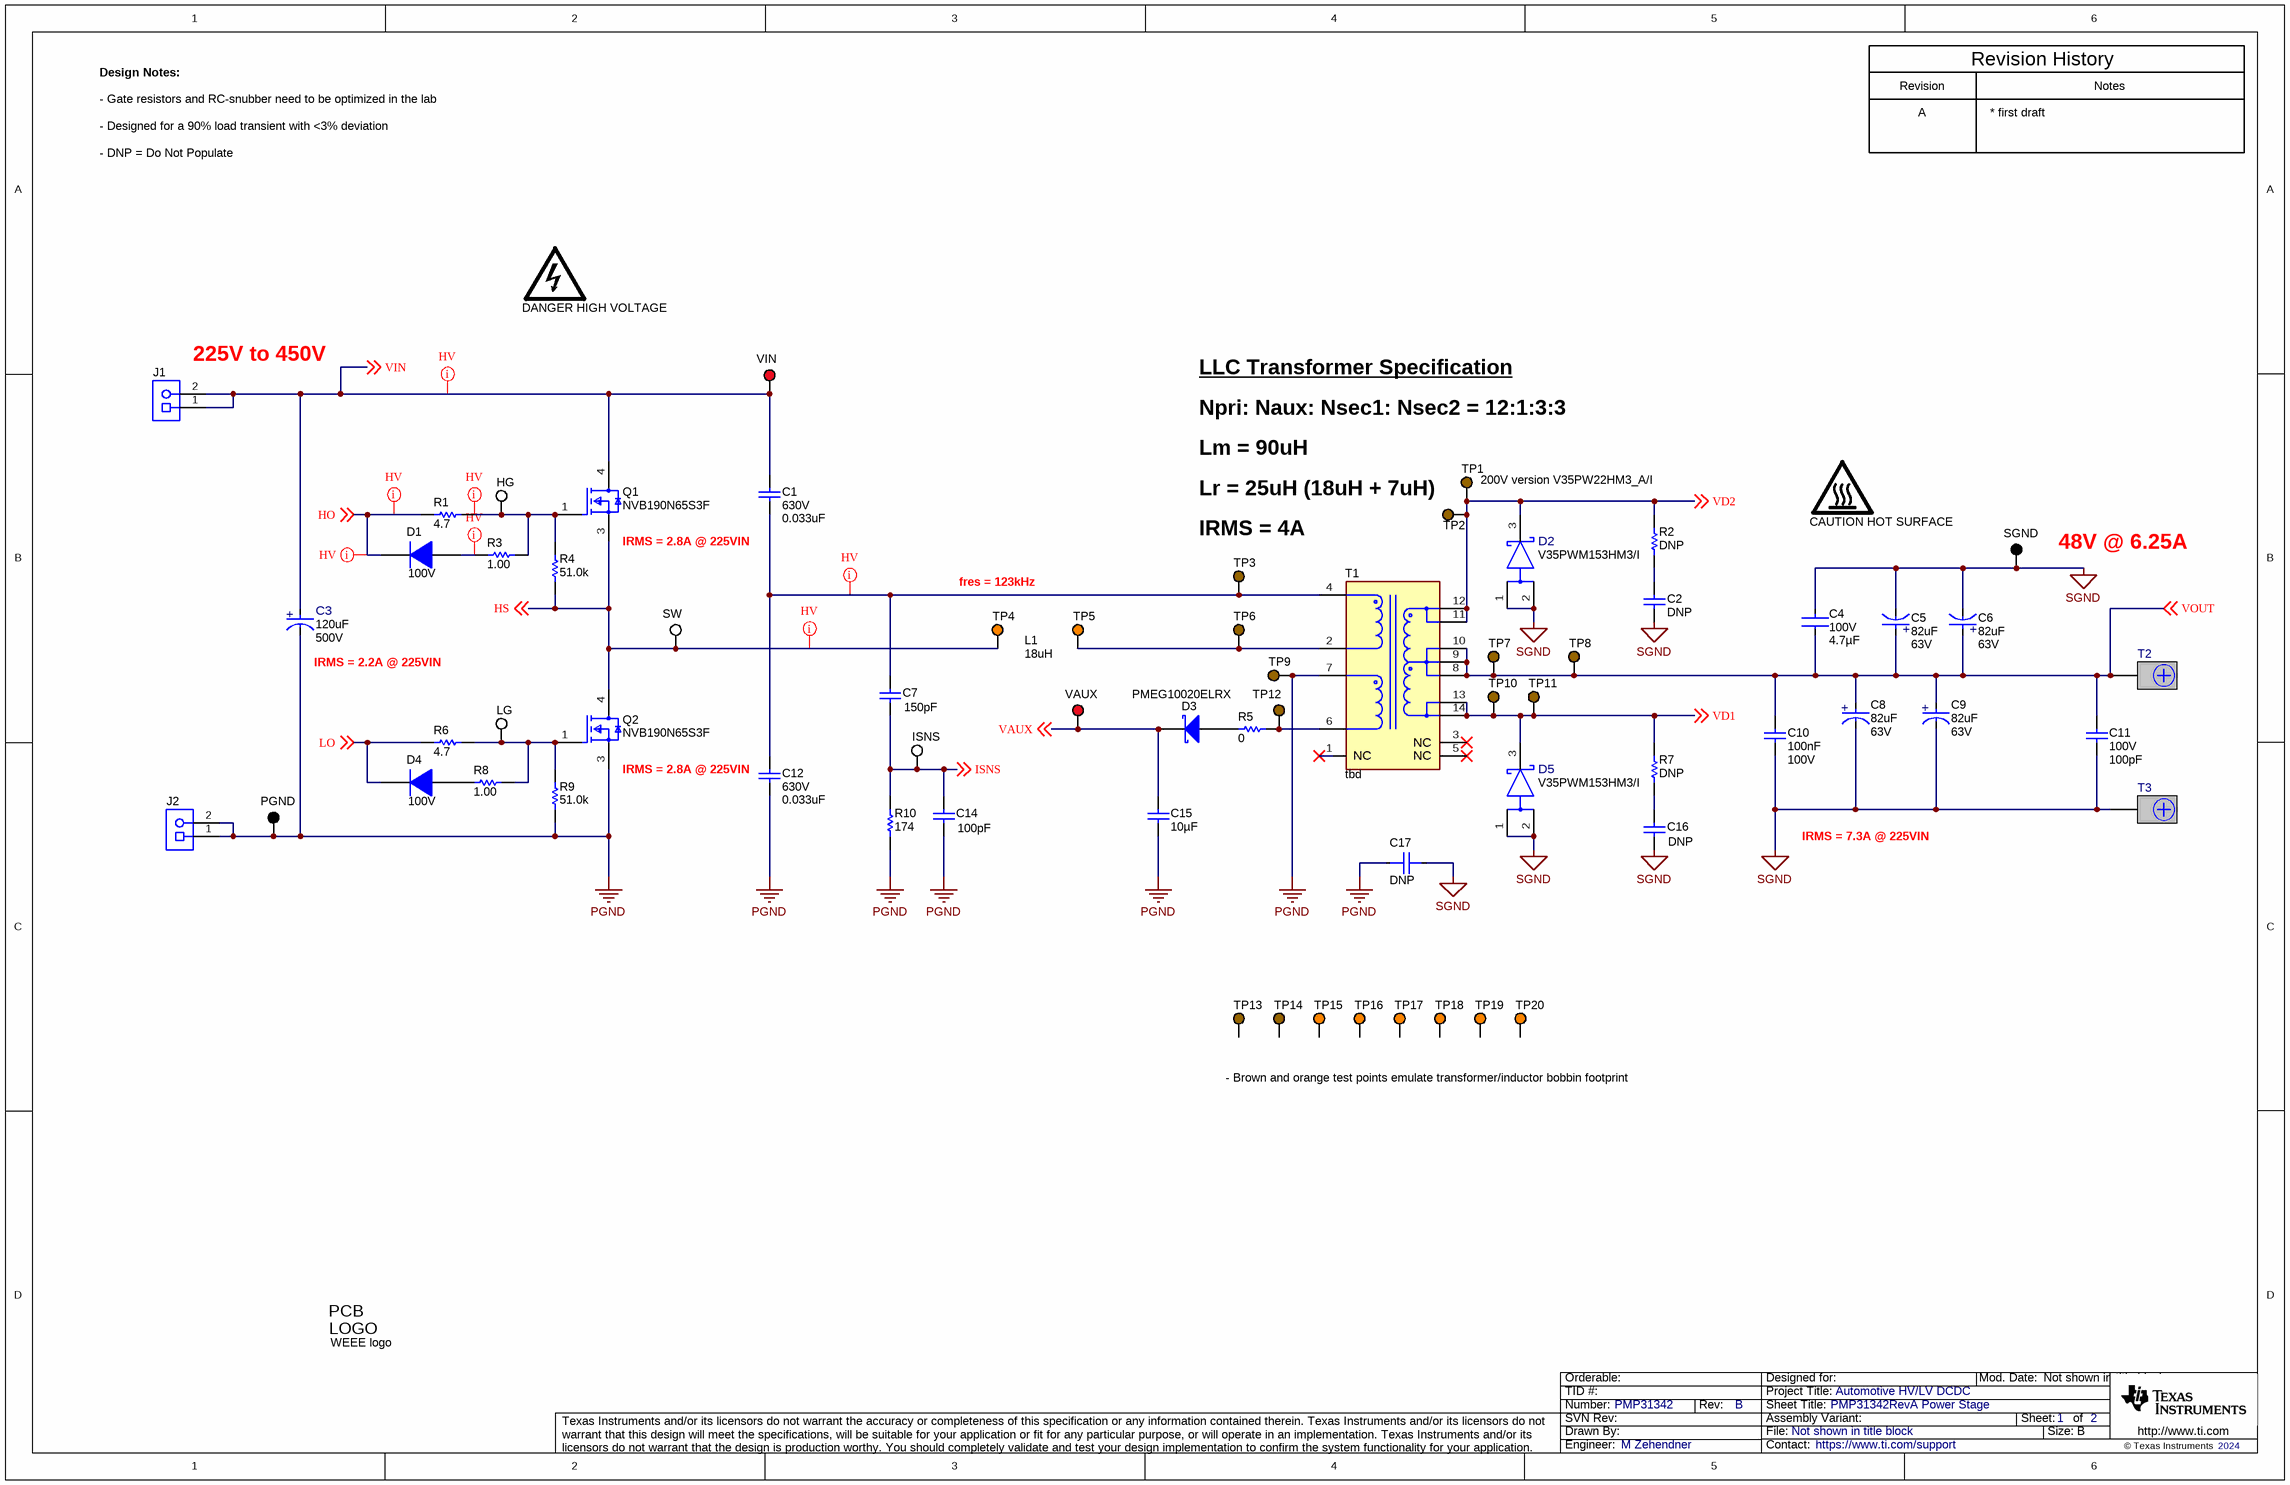
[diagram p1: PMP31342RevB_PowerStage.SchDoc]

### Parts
C1  VDC_V: 630V  ValueDisplayed: 0.033uF  [CAPRR1500W80L1800T500H1050]  (hidden comment: B32641B6333)
C2  ValueDisplayed: DNP  [0805L]  (hidden comment: GRM2165C2A122JA01D)
C3  ValueDisplayed: 120uF  VDC_V: 500V  [FP-ALA8AD121BC500_RADIAL-MFG]  (hidden comment: ALA8AD121BC500)
C4  Cap_F: 4.7µF  VDC_V: 100V  [FP-CNA6P1X7R2A475K250AE_1210-MFG]  (hidden comment: CNA6P1X7R2A475K250AE)
C5  ValueDisplayed: 82uF  VDC_V: 63V  [FP-HHXF630ARA820MJA0G_RADIAL-MFG]  (hidden comment: HHXF630ARA820MJA0G)
C6  ValueDisplayed: 82uF  VDC_V: 63V  [FP-HHXF630ARA820MJA0G_RADIAL-MFG]  (hidden comment: HHXF630ARA820MJA0G)
C7  ValueDisplayed: 150pF  [1206L]  (hidden comment: GRM31A5C2J151JW01D)
C8  ValueDisplayed: 82uF  VDC_V: 63V  [FP-HHXF630ARA820MJA0G_RADIAL-MFG]  (hidden comment: HHXF630ARA820MJA0G)
C9  ValueDisplayed: 82uF  VDC_V: 63V  [FP-HHXF630ARA820MJA0G_RADIAL-MFG]  (hidden comment: HHXF630ARA820MJA0G)
C10  Cap_F: 100nF  VDC_V: 100V  [0805_HV]  (hidden comment: GCM21BR72A104KA37L)
C11  VDC_V: 100V  ValueDisplayed: 100pF  [0805_HV]  (hidden comment: GCM2165C2A101JA16D)
C12  VDC_V: 630V  ValueDisplayed: 0.033uF  [CAPRR1500W80L1800T500H1050]  (hidden comment: B32641B6333)
C14  ValueDisplayed: 100pF  [1206L]  (hidden comment: 12061A101JAT2A)
C15  ValueDisplayed: 10µF  [1206_180]  (hidden comment: C1206C106J3RACAUTO)
C16  ValueDisplayed: DNP  [0805L]  (hidden comment: GRM2165C2A122JA01D)
C17  ValueDisplayed: DNP  [FP-CS95ZU2GA332MANKA_RADIAL-MFG]  (hidden comment: CS95ZU2GA332MANKA)
D1  Vr_V: 100V  [SOD-123]  (hidden comment: 1N4148W-7-F)
D2  V35PWM153HM3/I  [FP-V35PWM153-M3_I_TO-252AE-MFG]
D3  PMEG10020ELRX  [SOD-123W]
D4  Vr_V: 100V  [SOD-123]  (hidden comment: 1N4148W-7-F)
D5  V35PWM153HM3/I  [FP-V35PWM153-M3_I_TO-252AE-MFG]
HG  5012  [Keystone5012]  (value not drawn)
ISNS  5012  [Keystone5012]  (value not drawn)
J1  ED120/2DS  [On-Shore_ED120_2DS]  (value not drawn)
J2  ED120/2DS  [On-Shore_ED120_2DS]  (value not drawn)
LG  5012  [Keystone5012]  (value not drawn)
LOGO1  DANGER HIGH VOLTAGE  [IEC_HighVoltage_Small]  (no BOM)
Logo2  CAUTION HOT SURFACE  [IEC_HotSurface_Small]  (no BOM)
Logo3  WEEE logo  [WEEE_Minimum]  (no BOM)
PGND  5011  [Keystone5011]  (value not drawn)
Q1  NVB190N65S3F  [FP-FDD86252_D2PAK-MFG]
Q2  NVB190N65S3F  [FP-FDD86252_D2PAK-MFG]
R1  ValueDisplayed: 4.7  [0603]  (hidden comment: CRCW06034R70JNEA)
R2  ValueDisplayed: DNP  [1206L]  (hidden comment: RC1206FR-0710RL)
R3  ValueDisplayed: 1.00  [0603L]  (hidden comment: RC0603FR-071RL)
R4  ValueDisplayed: 51.0k  [0603L]  (hidden comment: RC0603FR-0751KL)
R5  ValueDisplayed: 0  [1206L]  (hidden comment: ERJ-8GEY0R00V)
R6  ValueDisplayed: 4.7  [0603]  (hidden comment: CRCW06034R70JNEA)
R7  ValueDisplayed: DNP  [1206L]  (hidden comment: RC1206FR-0710RL)
R8  ValueDisplayed: 1.00  [0603L]  (hidden comment: RC0603FR-071RL)
R9  ValueDisplayed: 51.0k  [0603L]  (hidden comment: RC0603FR-0751KL)
R10  ValueDisplayed: 174  [1206]  (hidden comment: CRCW1206174RFKEA)
SGND  5011  [Keystone5011]  (value not drawn)
SW  5012  [Keystone5012]  (value not drawn)
T1  tbd  [FP-750320617_PTH_XFRMR_36MM5_43MM0-MFG]
T2  CXS70-14-C  [Panduit_CXS70-14-C]  (value not drawn)
T3  CXS70-14-C  [Panduit_CXS70-14-C]  (value not drawn)
TP1  5125  [Keystone5125]  (value not drawn)
TP2  5125  [Keystone5125]  (value not drawn)
TP3  5125  [Keystone5125]  (value not drawn)
TP4  5003  [Keystone5003]  (value not drawn)
TP5  5003  [Keystone5003]  (value not drawn)
TP6  5125  [Keystone5125]  (value not drawn)
TP7  5125  [Keystone5125]  (value not drawn)
TP8  5125  [Keystone5125]  (value not drawn)
TP9  5125  [Keystone5125]  (value not drawn)
TP10  5125  [Keystone5125]  (value not drawn)
TP11  5125  [Keystone5125]  (value not drawn)
TP12  5125  [Keystone5125]  (value not drawn)
TP13  5125  [Keystone5125]  (value not drawn)
TP14  5125  [Keystone5125]  (value not drawn)
TP15  5003  [Keystone5003]  (value not drawn)
TP16  5003  [Keystone5003]  (value not drawn)
TP17  5003  [Keystone5003]  (value not drawn)
TP18  5003  [Keystone5003]  (value not drawn)
TP19  5003  [Keystone5003]  (value not drawn)
TP20  5003  [Keystone5003]  (value not drawn)
VAUX  5010  [Keystone5010]  (value not drawn)
VIN  5010  [Keystone5010]  (value not drawn)

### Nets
PGND: C3.1(CATHODE) C12.2 C14.2 C15.2 C17.1 J2.1 J2.2 PGND.1 Q2.3(S) R9.1 R10.1 T1.7 TP9.1
SGND: C2.2 C4.1 C5.1(CATHODE) C6.1(CATHODE) C8.1(CATHODE) C9.1(CATHODE) C10.2 C11.2 C16.2 C17.2 D2.1(ANODE) D2.2(ANODE) D5.1(ANODE) D5.2(ANODE) SGND.1 T3.1
HO: D1.1(K) R1.1 ; off-sheet HO
HS: Q1.3(S) Q2.4(D) R4.1 SW.1 TP4.1 ; off-sheet HS
ISNS: C7.2 C14.1 ISNS.1 R10.2 ; off-sheet ISNS
LO: D4.1(K) R6.1 ; off-sheet LO
VAUX: C15.1 D3.1(K) VAUX.1 ; off-sheet VAUX
VD1: D5.3(CATHODE) R7.2 T1.13 T1.14 TP10.1 TP11.1 ; off-sheet VD1
VD2: D2.3(CATHODE) R2.2 T1.11 T1.12 TP1.1 TP2.1 ; off-sheet VD2
VIN: C1.1 C3.2(ANODE) J1.1 J1.2 Q1.4(D) VIN.1 ; off-sheet VIN
VOUT: C4.2 C5.2(ANODE) C6.2(ANODE) C8.2(ANODE) C9.2(ANODE) C10.1 C11.1 T1.8 T1.9 T1.10 T2.1 TP7.1 TP8.1 ; off-sheet VOUT
NetC1_2: C1.2 C7.1 C12.1 T1.4 TP3.1
NetC2_1: C2.1 R2.1
NetC16_1: C16.1 R7.1
NetD1_2: D1.2(A) R3.1
NetD3_2: D3.2(A) R5.1
NetD4_2: D4.2(A) R8.1
NetHG_1: HG.1 Q1.1(G) R1.2 R3.2 R4.2
NetLG_1: LG.1 Q2.1(G) R6.2 R8.2 R9.2
NetR5_2: R5.2 T1.6 TP12.1
NetT1_2: T1.2 TP5.1 TP6.1

Not connected (* = marked no-connect by the designer): T1 1(NC)* 3(NC)* 5(NC)*; TP13 1; TP14 1; TP15 1; TP16 1; TP17 1; TP18 1; TP19 1; TP20 1

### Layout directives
net class HV: HO, HS, NetC1_2, NetD1_2, NetHG_1, VIN

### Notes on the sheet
- Design Notes:
- - Gate resistors and RC-snubber need to be optimized in the lab
- Revision
- Revision History
- Notes
- - DNP = Do Not Populate
- - Designed for a 90% load transient with <3% deviation
- A
- * first draft
- (near J1) 225V to 450V
- LLC Transformer Specification
- Npri: Naux: Nsec1: Nsec2 = 12:1:3:3
- Lm = 90uH
- Lr = 25uH (18uH + 7uH)
- (near TP1) 200V version V35PW22HM3_A/I
- (near Q1) IRMS = 2.8A @ 225VIN
- (near TP3) IRMS = 4A
- (near SGND) 48V @ 6.25A
- fres = 123kHz
- (near C3) IRMS = 2.2A @ 225VIN
- 18uH
- L1
- IRMS = 2.8A @ 225VIN
- IRMS = 7.3A @ 225VIN
- - Brown and orange test points emulate transformer/inductor bobbin footprint

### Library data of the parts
C1 C12 = CMP-0012454-3: CAP, Film, 0.033 uF, 630 V, +/- 10%, TH; Manufacturer: TDK; TaMin_C: -40°C; Polarized: N; SizeAreaWB_mm2: 140; Value1: Unknown; TaMax_C: 105°C; SizeZ_mm: 13.0; SizeX_mm: 14; SizeY_mm: 6; Cap_Case: CAP_14x13.0x6mm; AEC Qualified: Y; Cap_F: 33nF; AEC Category: Q200
C2 C16 = CMP-0008098-2: CAP, CERM, 1200 pF, 100 V, +/- 5%, C0G/NP0, 0805; Manufacturer: MuRata; TaMin_C: -55°C; Polarized: N; SizeAreaWB_mm2: 6.75; Value1: Unknown; U/M: EA; Value: 1200pF; TaMax_C: 125°C; SizeZ_mm: 1.45; SizeX_mm: 2; SizeY_mm: 1.25; Cap_Case: 0805; Value2: 100V; SizeArea_mm2: 2.5; Cap_F: 1.2nF; AEC Category: Q200
C3 = CMP-0122768-1: 120 µF 500 V Aluminum Electrolytic Capacitors Radial, Can - Snap-In 1.73Ohm @ 100Hz 5000 Hrs @ 105°C; Manufacturer: KEMET; AEC Grade: Grade 2; AEC Qualified: Yes; Cap_F: 120µF; IRMS_A: 1.1A; SizeZ_mm: 37mm; Tolerance_%: 20%; Esr: 1.73; Leakage Current: 180uA; Life: 5000Hours; Value: 120µF
C4 = CMP-0087262-1: CAP CER 4.7UF 100V X7R 1210; Manufacturer: TDK; Tolerance_%: 10%; TempCo: 15%; Symbol Name: SYM-CNA6P1X7R2A475K250AE; AEC Qualified: Yes; AEC Grade: Grade 1; SizeZ_mm: 2.8mm
C5 C6 C8 C9 = CMP-0122751-1: 82 µF 63 V Aluminum - Polymer Capacitors Radial, Can - SMD 22mOhm 3000 Hrs @ 135°C; Manufacturer: United Chemi-Con; AEC Grade: Grade 1; AEC Qualified: Yes; Cap_F: 82µF; IRMS_A: 4A; SizeZ_mm: 10.5mm; Tolerance_%: 20%; Dissipation Factor: 8%; Esr: 22m; Leakage Current: 51.6uA; Life: 4000Hours; Value: 82µF
C7 = CMP-0008885-2: CAP, CERM, 150 pF, 630 V, +/- 5%, C0G/NP0, 1206; Manufacturer: MuRata; TaMin_C: -55°C; Polarized: N; SizeAreaWB_mm2: 10.92; Value1: Unknown; U/M: EA; Value: 150pF; TaMax_C: 125°C; SizeZ_mm: 1.35; SizeX_mm: 3.2; SizeY_mm: 1.6; Cap_Case: 1206; Value2: 630V; SizeArea_mm2: 5.12; CompType: Capacitor; AEC Category: Q200
C10 = CMP-0860440-1: CAP, CERM, 0.1 µF, 100 V,+/- 10%, X7R, AEC-Q200 Grade 1, 0805; Manufacturer: MuRata; SizeY_mm: 1.25; ValueDisplayed: 0.1µF; SizeX_mm: 2; Cap_Case: 0805; AEC Grade: 1; Polarized: N; Value: 0.1uF; TaMin_C: -55°C; SizeZ_mm: 1.45; TaMax_C: 125°C; U/M: EA; SizeArea_mm2: 2.5; AEC Qualified: Y; SizeAreaWB_mm2: 6.75; AEC Category: Q200
C11 = CMP-0008009-2: CAP, CERM, 100 pF, 100 V, +/- 5%, C0G/NP0, AEC-Q200 Grade 1, 0805; Manufacturer: MuRata; TaMin_C: -55°C; Polarized: N; SizeAreaWB_mm2: 6.75; Value1: Unknown; U/M: EA; Value: 100pF; TaMax_C: 105°C; SizeZ_mm: 1.45; SizeX_mm: 2; SizeY_mm: 1.25; Cap_Case: 0805; SizeArea_mm2: 2.5; AEC Qualified: Y; AEC Grade: 1; AEC Category: Q200
C14 = CMP-0008462-2: CAP, CERM, 100 pF, 100 V, +/- 5%, C0G/NP0, 1206; Manufacturer: AVX; TaMin_C: -55°C; ESR_ohm: 7.01d; Polarized: N; SizeAreaWB_mm2: 10.92; Value1: 0.701 ohm; U/M: EA; Value: 100pF; TaMax_C: 125°C; SizeZ_mm: 1.35; SizeX_mm: 3.2; SizeY_mm: 1.6; Cap_Case: 1206; Value2: 100V; SizeArea_mm2: 5.12; CompType: Capacitor; AEC Category: Q200
C15 = CMP-0081062-1: CAP, CERM, 10 µF, 25 V,+/- 5%, X7R, AEC-Q200 Grade 1, 1206; Manufacturer: Kemet; TaMin_C: -55°C; Polarized: N; SizeAreaWB_mm2: 10.92; U/M: EA; Value: 10uF; TaMax_C: 125°C; SizeZ_mm: 1.8; SizeX_mm: 3.2; SizeY_mm: 1.6; Value2: 25V; SizeArea_mm2: 5.12; AEC Qualified: Y; AEC Grade: 1; AEC Category: Q200
C17 = CMP-0097517-1: Capacitor Ceramic 0.0033uF 440V/300V 20% 7.5mm Radial Bulk; Manufacturer: TDK; SizeZ_mm: 16mm; Voltage Ac Rating Y: 300V; Temperature Characteristic: Z5U; Voltage Ac Rating X: 440V; AEC Qualified: Yes; Value: 3.3nF; TempCo: +22/-56%; AEC Grade: Grade 1
D1 D4 = CMP-0029001-2: Diode, Ultrafast, 100 V, 0.15 A, SOD-123; Manufacturer: Diodes Inc.; Io_A: 150mA; Green_Lifecycle: Active; SizeAreaWB_mm2: 13.095; Green_REACh: Passed; Value1: 0.15A; TJmax_C: 150°C; Value: 100V; SizeZ_mm: 1.35; SizeX_mm: 3.85; SizeY_mm: 1.7; Vf_V: 1.25V; SizeArea_mm2: 6.545; AEC Category: Q101
D2 D5 = CMP-0049616-2: Diode 150 V 35A Surface Mount SlimDPAK; Manufacturer: Vishay; PartNumber: V35PWM153-M3/I; AEC Qualified: No; SizeZ_mm: 1.6mm; TJmax_C: 175°C; Vf_V: 150V; Cap_F: 1420pF; Max Surge Forward Current: 260A; Peak Reverse Current: 0.2mA; Standoff Height: 0mm; AEC Category: Q101
D3 = CMP-0028977-2: Diode, Schottky, 100 V, 2 A, AEC-Q101, SOD-123W; Manufacturer: Nexperia; Io_A: 2A; SizeAreaWB_mm2: 12.15; Vr_V: 100V; TJmax_C: 175°C; Value: 100V; SizeZ_mm: 1; SizeX_mm: 3.5; SizeY_mm: 1.7; Vf_V: 830mV; Value2: 0.83V; SizeArea_mm2: 5.95; AEC Qualified: Y; AEC Category: Q101
HG ISNS LG SW = CMP-0055149-2: as BLK on sheet PMP31342RevB_Control
J1 J2 = CMP-0074910-1: Terminal Block, 5.08 mm, 2x1, Brass, TH; Manufacturer: On-Shore Technology; Cert_VDE: Y; CNHeader: False; Current_A: 15A; Green_Lifecycle: Not Set; Shrouded: N; Gender: Female; Green_REACh: Incomplete; Voltage_V: 300V; Row_Count: 1; Pitch_mm: 5.08; CT: True
LOGO1 = CMP-0074835-1: IEC 61010-1 High Voltage Warning; SymbolCreator: a0412235
Logo2 = CMP-0074837-2: IEC 61010-1 Hot Surface Warning; Manufacturer: Texas Instruments; CompType: IC; AEC Category: Q200; SymbolCreator: a0412235
Logo3 = CMP-0074769-1
PGND SGND = CMP-0055148-2: Test Point, Multipurpose, Black, TH; Manufacturer: Keystone Electronics; CNHeader: FALSE; Green_Lifecycle: Active; Green_REACh: Passed; ContactFinish: Silver; CT: TRUE
Q1 Q2 = CMP-0122070-1: N-Channel 650 V, 20A (Tc), 162W (Tc) Surface Mount TO−263; Manufacturer: On Semi; AEC Qualified: Yes; QgTyp_nC: 34nC @ 10V; SizeZ_mm: 2.517mm; Vgs_V: 30V; ChMode: False; Drain To Source Breakdown Voltage: 650V; Input Capacitace At Vds: 1605pF @ 400V; Number Of Channels: 1; Pulse Drain Current: 50A; Reverse Recovery Charge: 220nC; Reverse Recovery Time: 68ns; Rthja Max: 40°C/W; Threshold Vgs Max: 4V; Threshold Vgs Min: 2V; TJmax_C: +150°C; Transconductance: 15S; Turn Off Delay Time: 43ns; Turn On Delay Time: 19ns; Typ Forward Diode Voltage: 1.0V
R1 R6 = CMP-0025821-4: RES, 4.7, 5%, 0.1 W, AEC-Q200 Grade 0, 0603; Manufacturer: Vishay-Dale; Power_W: 100mW; TempCo: 200 ppm/C; Value_Code: 4R70; Value: 4.7; EIA_Code: E24; SizeX_mm: 1.6; SizeY_mm: 0.8; SizeZ_mm: 1; Value2: 0.1W; SizeArea_mm2: 1.28; AEC Qualified: Y; VDC_V: 75V; AEC Category: Q200; AEC Grade: 0
R2 R7 = CMP-0017851-2: RES, 10.0, 1%, 0.25 W, 1206; Manufacturer: Yageo America; Power_W: 250mW; TempCo: 200 ppm/C; Value_Code: 10R0; U/M: EA; Value: 10.0; EIA_Code: E96; Res_ohm: 10; SizeX_mm: 3.2; SizeY_mm: 1.6; SizeZ_mm: 1.35; Value2: 0.25W; SizeArea_mm2: 5.12; VDC_V: 200V; AEC Category: Q200
R3 R8 = CMP-0022900-4: RES, 1.00, 1%, 0.1 W, 0603; Manufacturer: Yageo; Power_W: 100mW; TempCo: 200 ppm/C; Value_Code: 1R00; Value: 1.00; EIA_Code: E96; Res_ohm: 1; SizeX_mm: 1.6; SizeY_mm: 0.8; Value2: 0.1W; SizeArea_mm2: 1.28; CompType: Resistor; AEC Qualified: N; VDC_V: 75V; AEC Category: Q200; SizeAreaWB_mm2: 4.68
R4 R9 = CMP-0023167-5: RES, 51.0 k, 1%, 0.1 W, 0603; Manufacturer: Yageo; Power_W: 100mW; TempCo: 100 ppm/C; Value_Code: 51k0; Value: 51.0k; Res_ohm: 51k; SizeX_mm: 1.6; SizeY_mm: 0.8; SizeZ_mm: 1; Value2: 0.1W; SizeArea_mm2: 1.28; AEC Qualified: N; VDC_V: 75V; AEC Category: Q200; SizeAreaWB_mm2: 4.68
R5 = CMP-0018748-3: RES, 0, 5%, 0.25 W, AEC-Q200 Grade 0, 1206; Manufacturer: Panasonic; Power_W: 250mW; TempCo: 600 ppm/C; Value_Code: 0000; Value: 0; EIA_Code: E24; SizeX_mm: 3.2; SizeY_mm: 1.6; SizeZ_mm: 1.35; Value2: 0.25W; SizeArea_mm2: 5.12; AEC Qualified: Y; VDC_V: 200V; AEC Category: Q200; SizeAreaWB_mm2: 10.92
R10 = CMP-0016664-3: RES, 174, 1%, 0.25 W, AEC-Q200 Grade 0, 1206; Manufacturer: Vishay-Dale; Power_W: 250mW; TempCo: 100 ppm/C; Value_Code: 174R; Value: 174; EIA_Code: E96; SizeX_mm: 3.2; SizeY_mm: 1.6; SizeZ_mm: 1.35; Value2: 0.25W; SizeArea_mm2: 5.12; AEC Qualified: Y; VDC_V: 200V; AEC Category: Q200; AEC Grade: 0
T1 = CMP-0065589-1: TRANSFORMER-; Manufacturer: Wurth Electronics; PartNumber: 750320617; DCR_ohm: 0.135; Ind_H: 510µH; Ns1toNp: 16.5:1; Rsec1_ohm: 5m; SizeZ_mm: 26.5mm; AEC Qualified: No; Frequency_Fixed: 60-130kHz; Voltage_Isolation_Vrms: 3kV
T2 T3 = CMP-0075010-2: Terminal 70A Lug; Manufacturer: Panduit; CNHeader: False; Green_Lifecycle: Not Set; Green_REACh: Incomplete; CompType: Screw Terminal
TP1-TP3 TP6-TP14 = CMP-0055157-2: Test Point, Multipurpose, Brown, TH; Manufacturer: Keystone Electronics; CT: TRUE; Green_Lifecycle: Active; CNHeader: FALSE; ContactFinish: Silver; Green_REACh: Passed
TP4 TP5 TP15-TP20 = CMP-0055140-2: Test Point, Miniature, Orange, TH; Manufacturer: Keystone Electronics; Green_Lifecycle: Active; ContactFinish: Silver; CNHeader: FALSE; CT: TRUE; Green_REACh: Passed
VAUX VIN = CMP-0055147-2: as 5V on sheet PMP31342RevB_Control

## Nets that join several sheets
PGND: PMP31342RevB_Control (20 pins), PMP31342RevB_PowerStage (13 pins)
SGND: PMP31342RevB_Control (C101.2 D8.2 R40.1 U3.5), PMP31342RevB_PowerStage (16 pins)
HO: PMP31342RevB_Control (U1.15), PMP31342RevB_PowerStage (D1.1 R1.1)
HS: PMP31342RevB_Control (C21.2 U1.16), PMP31342RevB_PowerStage (5 pins)
ISNS: PMP31342RevB_Control (U1.9), PMP31342RevB_PowerStage (C7.2 C14.1 ISNS.1 R10.2)
LO: PMP31342RevB_Control (U1.11), PMP31342RevB_PowerStage (D4.1 R6.1)
VAUX: PMP31342RevB_Control (5 pins), PMP31342RevB_PowerStage (C15.1 D3.1 VAUX.1)
VIN: PMP31342RevB_Control (R14.2 R15.1), PMP31342RevB_PowerStage (6 pins)
VOUT: PMP31342RevB_Control (R23.2 VOUT.1), PMP31342RevB_PowerStage (13 pins)

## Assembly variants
PMP31342 with smaller Cr: alternate parts C1 -> CMP-0124191-1, C12 -> CMP-0124191-1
